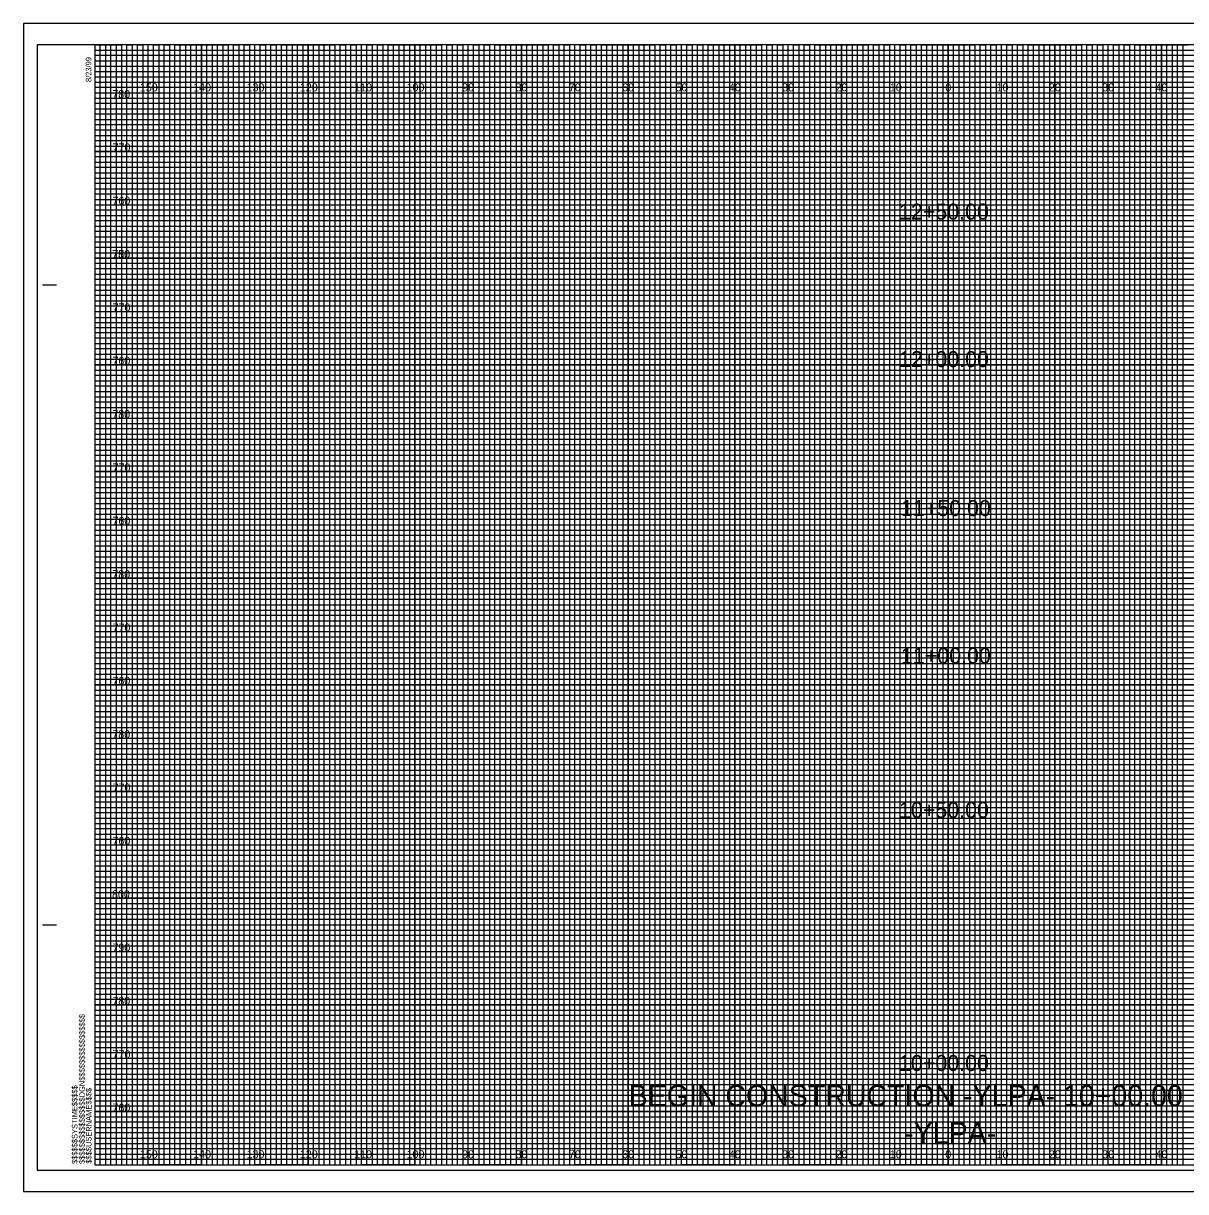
# Model space of a CAD drawing. Extents: x -13 to 323, y -5 to 214.
# Drawn here: x -13.4 to 204.5, y -5 to 214 of the extents above; entities that cross this region are included whole.
import ezdxf

# ---------------------------------------------------------------- set-up
doc = ezdxf.new("R2010")
doc.units = 0
for name, color, linetype in [('Exist Cross Section Cell', 7, 'Continuous'), ('Exist XS Center Line Elevation Label', 7, 'Continuous'), ('Exist XS Ground Line', 7, 'Continuous'), ('Prop XS Ditch Standard Text', 7, 'Continuous'), ('Prop XS Dump Level', 7, 'Continuous'), ('Prop XS EOT Tick Mark', 7, 'Continuous'), ('Prop XS Finish Grade', 7, 'Continuous'), ('Prop XS Finish Grade Earthwork', 7, 'Continuous'), ('Prop XS Hydro Typical Ditch Data', 7, 'Continuous'), ('Prop XS SE Text', 7, 'Continuous'), ('Prop XS Side Slope Text', 7, 'Continuous'), ('Prop XS SS Elevation Text', 7, 'Continuous'), ('Prop XS Subgrade Earthwork', 7, 'Continuous')]:
    doc.layers.add(name, color=color, linetype=linetype)

msp = doc.modelspace()

# ---------------------------------------------------------------- linework, layer by layer
at = {"layer": 'Exist XS Center Line Elevation Label'}
for points in [[(0, 210), (5, 210), (5, 0), (15, 0), (15, 210), (25, 210), (25, 0), (35, 0), (35, 210), (45, 210), (45, 0), (55, 0), (55, 210), (65, 210), (65, 0), (75, 0), (75, 210), (85, 210), (85, 0), (95, 0), (95, 210), (105, 210), (105, 0), (115, 0), (115, 210), (125, 210), (125, 0), (135, 0), (135, 210), (145, 210), (145, 0), (155, 0), (155, 210), (165, 210), (165, 0), (175, 0), (175, 210), (185, 210), (185, 0), (195, 0), (195, 210), (205, 210)], [(0, 205), (275, 205)], [(0, 185), (320, 185), (320, 195), (0, 195)], [(0, 165), (320, 165), (320, 175), (0, 175)], [(0, 145), (320, 145), (320, 155), (0, 155)], [(0, 125), (320, 125), (320, 135), (0, 135)], [(0, 105), (320, 105), (320, 115), (0, 115)], [(0, 85), (320, 85), (320, 95), (0, 95)], [(0, 65), (320, 65), (320, 75), (0, 75)], [(0, 45), (320, 45), (320, 55), (0, 55)], [(0, 25), (320, 25), (320, 35), (0, 35)], [(0, 5), (320, 5), (320, 15), (0, 15)]]:
    msp.add_lwpolyline(points, dxfattribs=at)
at = {"layer": 'Exist XS Ground Line'}
for p, q in [((10, 210), (0, 210)), ((10, 0), (10, 210)), ((30, 210), (20, 210)), ((20, 210), (20, 0)), ((30, 0), (30, 210)), ((50, 210), (40, 210)), ((40, 210), (40, 0)), ((50, 0), (50, 210)), ((70, 210), (60, 210)), ((60, 210), (60, 0)), ((70, 0), (70, 210)), ((90, 210), (80, 210)), ((80, 210), (80, 0)), ((90, 0), (90, 210)), ((110, 210), (100, 210)), ((100, 210), (100, 0)), ((110, 0), (110, 210)), ((130, 210), (120, 210)), ((120, 210), (120, 0)), ((130, 0), (130, 210)), ((150, 210), (140, 210)), ((140, 210), (140, 0)), ((150, 0), (150, 210)), ((170, 210), (160, 210)), ((160, 210), (160, 0)), ((170, 0), (170, 210)), ((190, 210), (180, 210)), ((180, 210), (180, 0)), ((190, 0), (190, 210)), ((210, 210), (200, 210)), ((200, 210), (200, 0)), ((20, 0), (10, 0)), ((40, 0), (30, 0)), ((60, 0), (50, 0)), ((80, 0), (70, 0)), ((100, 0), (90, 0)), ((120, 0), (110, 0)), ((140, 0), (130, 0)), ((160, 0), (150, 0)), ((180, 0), (170, 0)), ((200, 0), (190, 0))]:
    msp.add_line(p, q, dxfattribs=at)
for points in [[(0, 200), (320, 200), (320, 190), (0, 190)], [(0, 180), (320, 180), (320, 170), (0, 170)], [(0, 160), (320, 160), (320, 150), (0, 150)], [(0, 140), (320, 140), (320, 130), (0, 130)], [(0, 120), (320, 120), (320, 110), (0, 110)], [(0, 100), (320, 100), (320, 90), (0, 90)], [(0, 80), (320, 80), (320, 70), (0, 70)], [(0, 60), (320, 60), (320, 50), (0, 50)], [(0, 40), (320, 40), (320, 30), (0, 30)], [(0, 20), (320, 20), (320, 10), (0, 10)]]:
    msp.add_lwpolyline(points, dxfattribs=at)
at = {"layer": 'Prop XS Ditch Standard Text'}
for points in [[(0, 0), (1, 0), (1, 210), (2, 210), (2, 0)], [(2, 0), (3, 0), (3, 210), (4, 210), (4, 0)], [(5, 0), (6, 0), (6, 210), (7, 210), (7, 0)], [(7, 0), (8, 0), (8, 210), (9, 210), (9, 0)], [(10, 0), (11, 0), (11, 210), (12, 210), (12, 0)], [(12, 0), (13, 0), (13, 210), (14, 210), (14, 0)], [(15, 0), (16, 0), (16, 210), (17, 210), (17, 0)], [(17, 0), (18, 0), (18, 210), (19, 210), (19, 0)], [(20, 0), (21, 0), (21, 210), (22, 210), (22, 0)], [(22, 0), (23, 0), (23, 210), (24, 210), (24, 0)], [(25, 0), (26, 0), (26, 210), (27, 210), (27, 0)], [(27, 0), (28, 0), (28, 210), (29, 210), (29, 0)], [(30, 0), (31, 0), (31, 210), (32, 210), (32, 0)], [(32, 0), (33, 0), (33, 210), (34, 210), (34, 0)], [(35, 0), (36, 0), (36, 210), (37, 210), (37, 0)], [(37, 0), (38, 0), (38, 210), (39, 210), (39, 0)], [(40, 0), (41, 0), (41, 210), (42, 210), (42, 0)], [(42, 0), (43, 0), (43, 210), (44, 210), (44, 0)], [(45, 0), (46, 0), (46, 210), (47, 210), (47, 0)], [(47, 0), (48, 0), (48, 210), (49, 210), (49, 0)], [(50, 0), (51, 0), (51, 210), (52, 210), (52, 0)], [(52, 0), (53, 0), (53, 210), (54, 210), (54, 0)], [(55, 0), (56, 0), (56, 210), (57, 210), (57, 0)], [(57, 0), (58, 0), (58, 210), (59, 210), (59, 0)], [(60, 0), (61, 0), (61, 210), (62, 210), (62, 0)], [(62, 0), (63, 0), (63, 210), (64, 210), (64, 0)], [(65, 0), (66, 0), (66, 210), (67, 210), (67, 0)], [(67, 0), (68, 0), (68, 210), (69, 210), (69, 0)], [(70, 0), (71, 0), (71, 210), (72, 210), (72, 0)], [(72, 0), (73, 0), (73, 210), (74, 210), (74, 0)], [(75, 0), (76, 0), (76, 210), (77, 210), (77, 0)], [(77, 0), (78, 0), (78, 210), (79, 210), (79, 0)], [(80, 0), (81, 0), (81, 210), (82, 210), (82, 0)], [(82, 0), (83, 0), (83, 210), (84, 210), (84, 0)], [(85, 0), (86, 0), (86, 210), (87, 210), (87, 0)], [(87, 0), (88, 0), (88, 210), (89, 210), (89, 0)], [(90, 0), (91, 0), (91, 210), (92, 210), (92, 0)], [(92, 0), (93, 0), (93, 210), (94, 210), (94, 0)], [(95, 0), (96, 0), (96, 210), (97, 210), (97, 0)], [(97, 0), (98, 0), (98, 210), (99, 210), (99, 0)], [(100, 0), (101, 0), (101, 210), (102, 210), (102, 0)], [(102, 0), (103, 0), (103, 210), (104, 210), (104, 0)], [(105, 0), (106, 0), (106, 210), (107, 210), (107, 0)], [(107, 0), (108, 0), (108, 210), (109, 210), (109, 0)], [(110, 0), (111, 0), (111, 210), (112, 210), (112, 0)], [(112, 0), (113, 0), (113, 210), (114, 210), (114, 0)], [(115, 0), (116, 0), (116, 210), (117, 210), (117, 0)], [(117, 0), (118, 0), (118, 210), (119, 210), (119, 0)], [(120, 0), (121, 0), (121, 210), (122, 210), (122, 0)], [(122, 0), (123, 0), (123, 210), (124, 210), (124, 0)], [(125, 0), (126, 0), (126, 210), (127, 210), (127, 0)], [(127, 0), (128, 0), (128, 210), (129, 210), (129, 0)], [(130, 0), (131, 0), (131, 210), (132, 210), (132, 0)], [(132, 0), (133, 0), (133, 210), (134, 210), (134, 0)], [(135, 0), (136, 0), (136, 210), (137, 210), (137, 0)], [(137, 0), (138, 0), (138, 210), (139, 210), (139, 0)], [(140, 0), (141, 0), (141, 210), (142, 210), (142, 0)], [(142, 0), (143, 0), (143, 210), (144, 210), (144, 0)], [(145, 0), (146, 0), (146, 210), (147, 210), (147, 0)], [(147, 0), (148, 0), (148, 210), (149, 210), (149, 0)], [(150, 0), (151, 0), (151, 210), (152, 210), (152, 0)], [(152, 0), (153, 0), (153, 210), (154, 210), (154, 0)], [(155, 0), (156, 0), (156, 210), (157, 210), (157, 0)], [(157, 0), (158, 0), (158, 210), (159, 210), (159, 0)], [(160, 0), (161, 0), (161, 210), (162, 210), (162, 0)], [(162, 0), (163, 0), (163, 210), (164, 210), (164, 0)], [(165, 0), (166, 0), (166, 210), (167, 210), (167, 0)], [(167, 0), (168, 0), (168, 210), (169, 210), (169, 0)], [(170, 0), (171, 0), (171, 210), (172, 210), (172, 0)], [(172, 0), (173, 0), (173, 210), (174, 210), (174, 0)], [(175, 0), (176, 0), (176, 210), (177, 210), (177, 0)], [(177, 0), (178, 0), (178, 210), (179, 210), (179, 0)], [(180, 0), (181, 0), (181, 210), (182, 210), (182, 0)], [(182, 0), (183, 0), (183, 210), (184, 210), (184, 0)], [(185, 0), (186, 0), (186, 210), (187, 210), (187, 0)], [(187, 0), (188, 0), (188, 210), (189, 210), (189, 0)], [(190, 0), (191, 0), (191, 210), (192, 210), (192, 0)], [(192, 0), (193, 0), (193, 210), (194, 210), (194, 0)], [(195, 0), (196, 0), (196, 210), (197, 210), (197, 0)], [(197, 0), (198, 0), (198, 210), (199, 210), (199, 0)], [(200, 0), (201, 0), (201, 210), (202, 210), (202, 0)], [(202, 0), (203, 0), (203, 210), (204, 210), (204, 0)]]:
    msp.add_lwpolyline(points, dxfattribs=at)
at = {"layer": 'Prop XS Dump Level'}
for p, q in [((-9.8, 165), (-7.3, 165)), ((-9.7, 165), (-7.2, 165)), ((-9.8, 45), (-7.3, 45)), ((-9.7, 45), (-7.2, 45)), ((0, 0), (0, 0)), ((0, 0), (0, 0)), ((0, 0), (0, 0)), ((0, 0), (0, 0)), ((0, 0), (0, 0)), ((0, 0), (0, 0)), ((0, 0), (0, 0))]:
    msp.add_line(p, q, dxfattribs=at)
msp.add_lwpolyline([(320, 210), (0, 210), (0, 0), (320, 0)], close=True, dxfattribs=at)
at = {"layer": 'Prop XS Finish Grade Earthwork'}
for p, q in [((323.3, 214), (-13.4, 214)), ((-13.4, 214), (-13.4, -5)), ((-13.4, -5), (323.3, -5))]:
    msp.add_line(p, q, dxfattribs=at)
at = {"layer": 'Prop XS Hydro Typical Ditch Data'}
for p, q in [((10, 0), (10, 210)), ((20, 0), (20, 210)), ((30, 0), (30, 210)), ((40, 0), (40, 210)), ((50, 0), (50, 210)), ((60, 0), (60, 210)), ((70, 0), (70, 210)), ((80, 0), (80, 210)), ((90, 0), (90, 210)), ((100, 0), (100, 210)), ((110, 0), (110, 210)), ((120, 0), (120, 210)), ((130, 0), (130, 210)), ((140, 0), (140, 210)), ((150, 0), (150, 210)), ((160, 0), (160, 210)), ((170, 0), (170, 210)), ((180, 0), (180, 210)), ((190, 0), (190, 210)), ((200, 0), (200, 210)), ((0, 200), (320, 200)), ((0, 190), (320, 190)), ((0, 180), (320, 180)), ((0, 170), (320, 170)), ((0, 160), (320, 160)), ((0, 150), (320, 150)), ((0, 140), (320, 140)), ((0, 130), (320, 130)), ((0, 120), (320, 120)), ((0, 110), (320, 110)), ((0, 100), (320, 100)), ((0, 90), (320, 90)), ((0, 80), (320, 80)), ((0, 70), (320, 70)), ((0, 60), (320, 60)), ((0, 50), (320, 50)), ((0, 40), (320, 40)), ((0, 30), (320, 30)), ((0, 20), (320, 20)), ((0, 10), (320, 10))]:
    msp.add_line(p, q, dxfattribs=at)
at = {"layer": 'Prop XS SE Text'}
for p, q in [((0, 209), (260, 209)), ((260, 207.98), (0, 207.98)), ((0, 207.98), (0, 207)), ((0, 207), (260, 207)), ((260, 205.89), (0, 205.89)), ((0, 205.89), (0, 204)), ((0, 204), (320, 204))]:
    msp.add_line(p, q, dxfattribs=at)
for points in [[(0, 203), (270, 203), (320, 203), (320, 202), (0, 202)], [(0, 201), (320, 201), (320, 199), (0, 199)], [(0, 198), (320, 198), (320, 197), (0, 196.98)], [(0, 196), (320, 196), (320, 194), (0, 194)], [(0, 193), (320, 193), (320, 192), (0, 192)], [(0, 191), (320, 191), (320, 189), (0, 189)], [(0, 188), (320, 188), (320, 187), (0, 187)], [(0, 186), (320, 186), (320, 184), (0, 184)], [(0, 183), (320, 183), (320, 182), (0, 182)], [(0, 181), (320, 181), (320, 179), (0, 179)], [(0, 178), (320, 178), (320, 177), (0, 177)], [(0, 176), (320, 176), (320, 173.95), (320, 173), (320, 172), (0, 172)], [(0, 174), (320, 174), (320, 173), (0, 173)], [(0, 171), (320, 171), (320, 169), (0, 169.03)], [(0, 169.03), (320, 169), (320, 168), (0, 168)], [(0, 167), (320, 167), (320, 166), (0, 166)], [(0, 164), (320, 164), (320, 163), (0, 163)], [(0, 162), (320, 162), (320, 161), (0, 161)], [(-0.07, 158.89), (320, 158.89), (320, 157.88), (-0.07, 157.88)], [(0, 157), (320, 157), (320, 156), (0, 156)], [(0, 154), (320, 154), (320, 153), (0, 153)], [(0, 152), (320, 152), (320, 151), (0, 151)], [(0, 149), (320, 149), (320, 148), (0, 148)], [(0, 147), (320, 147), (320, 146), (0, 146)], [(0, 144), (320, 144), (320, 143), (0, 143)], [(0, 142), (320, 142), (320, 141), (0, 141)], [(0, 139), (320, 139), (319.99, 137.98), (0, 138)], [(0, 137), (320, 137), (320, 136), (0, 136)], [(0, 134), (320, 134), (320, 133), (0, 133)], [(0, 132), (320, 132), (320, 131), (0, 131)], [(0, 129), (320, 129), (320, 128), (0, 128)], [(0, 127), (320, 127), (320, 126), (0, 126)], [(0, 124), (320, 124), (320, 123), (0, 123)], [(0, 122), (320, 122), (320, 121), (0, 121)], [(0, 119), (320, 119), (320, 118), (0, 118)], [(0, 116.99), (320.07, 116.91), (320, 116), (0, 116)], [(0, 114), (320, 114), (320, 113), (0, 113)], [(0, 112), (320, 112), (320, 111), (0, 111)], [(0, 109), (320, 109), (320, 108), (0, 108)], [(0, 107), (320, 107), (320, 106), (0, 106)], [(0, 104), (320, 104), (320, 103), (0, 103)], [(0, 102), (320, 102), (320, 101), (0, 101)], [(0, 99), (320, 99), (320, 98), (0, 98)], [(0, 97), (320, 97), (320, 96), (0, 96)], [(0, 94), (320, 94), (320, 93), (0, 93)], [(0, 92), (320, 92), (320, 91), (0, 91)], [(0, 89), (320, 89), (320, 88), (0, 88)], [(0, 87), (320, 87), (320, 86), (0, 86)], [(0, 84), (320, 84), (320, 83), (0, 83)], [(0, 82), (320, 82), (320, 81), (0, 81)], [(0, 79), (320, 79), (319.99, 77.98), (0, 78)], [(0, 77), (320, 77), (320, 76), (0, 76)], [(0, 74), (320, 74), (320, 73), (0, 73)], [(0, 72), (320, 72), (320, 71), (0, 71)], [(0, 69), (320, 69), (320, 68), (0, 68)], [(0, 67), (320, 67), (320, 66), (0, 66)], [(0, 64), (320, 64), (320, 63), (0, 63)], [(0, 62), (320, 62), (320, 61), (0, 61)], [(0, 59), (320, 59), (320, 58), (0, 58)], [(0, 56.99), (320.07, 56.91), (320, 56), (0, 56)], [(0, 54), (320, 54), (320, 53), (0, 53)], [(0, 52), (320, 52), (320, 51), (0, 51)], [(0, 49), (320, 49), (320, 48), (0, 48)], [(0, 47), (320, 47), (320, 46), (0, 46)], [(0, 44), (320, 44), (320, 43), (0, 43)], [(0, 42), (320, 42), (320, 41), (0, 41)], [(0, 39), (320, 39), (320, 38), (0, 38)], [(0, 37), (320, 37), (320, 36), (0, 36)], [(0, 34), (320, 34), (320, 33), (0, 33)], [(0, 32), (320, 32), (320, 31), (0, 31)], [(0, 29), (320, 29), (320, 28), (0, 28)], [(0, 27), (320, 27), (320, 26), (0, 26)], [(0, 24), (320, 24), (320, 23), (0, 23)], [(0, 22), (320, 22), (320, 21), (0, 21)], [(0, 19), (320, 19), (320, 18), (0, 18)], [(0, 17), (320, 17), (320, 16), (0, 16)], [(0, 14), (320, 14), (320, 13), (0, 13)], [(0, 12), (320, 12), (320, 11), (0, 11)], [(0, 9), (320, 9), (320, 8), (0, 8)], [(0, 7), (320, 7), (320, 6), (0, 6)], [(0, 4), (320, 4), (320, 3), (0, 3)], [(0, 2), (320, 2), (320, 1), (0, 1)]]:
    msp.add_lwpolyline(points, dxfattribs=at)
at = {"layer": 'Prop XS Side Slope Text'}
msp.add_lwpolyline([(-13.4, -5), (323.3, -5), (323.3, 214), (-13.4, 214)], close=True, dxfattribs=at)
at = {"layer": 'Prop XS SS Elevation Text'}
msp.add_lwpolyline([(-10.8, -1), (322.4, -1), (322.4, 210), (-10.8, 210)], close=True, dxfattribs=at)

# ---------------------------------------------------------------- texts
at = {"layer": 'Exist Cross Section Cell'}
for s, p in [('150', (8.44, 201.25)), ('140', (18.44, 201.25)), ('130', (28.44, 201.25)), ('120', (38.44, 201.25)), ('110', (48.62, 201.25)), ('100', (58.44, 201.25)), ('90', (68.86, 201.25)), ('80', (78.86, 201.25)), ('70', (88.86, 201.25)), ('60', (98.86, 201.25)), ('50', (108.86, 201.25)), ('40', (118.86, 201.25)), ('30', (128.86, 201.25)), ('20', (138.86, 201.25)), ('10', (149.04, 201.25)), ('0', (159.45, 201.25)), ('0', (159.45, 201.25)), ('10', (169.04, 201.25)), ('20', (178.86, 201.25)), ('30', (188.86, 201.25)), ('40', (198.86, 201.25)), ('150', (8.44, 1.25)), ('140', (18.44, 1.25)), ('130', (28.44, 1.25)), ('120', (38.44, 1.25)), ('110', (48.62, 1.25)), ('100', (58.44, 1.25)), ('90', (68.86, 1.25)), ('80', (78.86, 1.25)), ('70', (88.86, 1.25)), ('60', (98.86, 1.25)), ('50', (108.86, 1.25)), ('40', (118.86, 1.25)), ('30', (128.86, 1.25)), ('20', (138.86, 1.25)), ('10', (149.04, 1.25)), ('0', (159.45, 1.25)), ('0', (159.45, 1.25)), ('10', (169.04, 1.25)), ('20', (178.86, 1.25)), ('30', (188.86, 1.25)), ('40', (198.86, 1.25))]:
    msp.add_text(s, height=1.5, dxfattribs=at).set_placement(p)
at = {"layer": 'Prop XS Dump Level'}
for s, p in [('8/23/99', (-0.65, 203)), ('$$$$$$$$$$$$$$$$DGN$$$$$$$$$$$$$$$$', (-1.88, 0.18)), ('$$$$$$SYSTIME$$$$$', (-3.26, 0.18)), ('$$$$USERNAME$$$$', (-0.62, 0.23))]:
    msp.add_text(s, height=1.05, rotation=90, dxfattribs=at).set_placement(p)
at = {"layer": 'Prop XS EOT Tick Mark'}
for s, p in [('BEGIN CONSTRUCTION -YLPA- 10+00.00', (100.08, 10.99)), ('-YLPA-', (151.74, 4))]:
    msp.add_text(s, height=4, dxfattribs=at).set_placement(p)
at = {"layer": 'Prop XS Finish Grade'}
for s, p in [('780', (3.28, 200)), ('770', (3.33, 190)), ('760', (3.3, 180)), ('750', (3.25, 170)), ('780', (3.28, 170)), ('770', (3.33, 160)), ('760', (3.3, 150)), ('780', (3.28, 140)), ('770', (3.33, 130)), ('760', (3.3, 120)), ('780', (3.28, 110)), ('770', (3.33, 100)), ('760', (3.3, 90)), ('780', (3.28, 80)), ('770', (3.33, 70)), ('760', (3.3, 60)), ('800', (3.22, 50)), ('790', (3.3, 40)), ('780', (3.28, 30)), ('770', (3.33, 20)), ('760', (3.3, 10))]:
    msp.add_text(s, height=1.5, dxfattribs=at).set_placement(p)
at = {"layer": 'Prop XS Subgrade Earthwork'}
for s, p in [('12+50.00', (150.77, 177.22)), ('12+00.00', (150.77, 149.56)), ('11+50.00', (151.13, 121.64)), ('11+00.00', (151.13, 93.98)), ('10+50.00', (150.77, 65.05)), ('10+00.00', (150.77, 17.61))]:
    msp.add_text(s, height=3, dxfattribs=at).set_placement(p)

doc.saveas('drawing.dxf')
